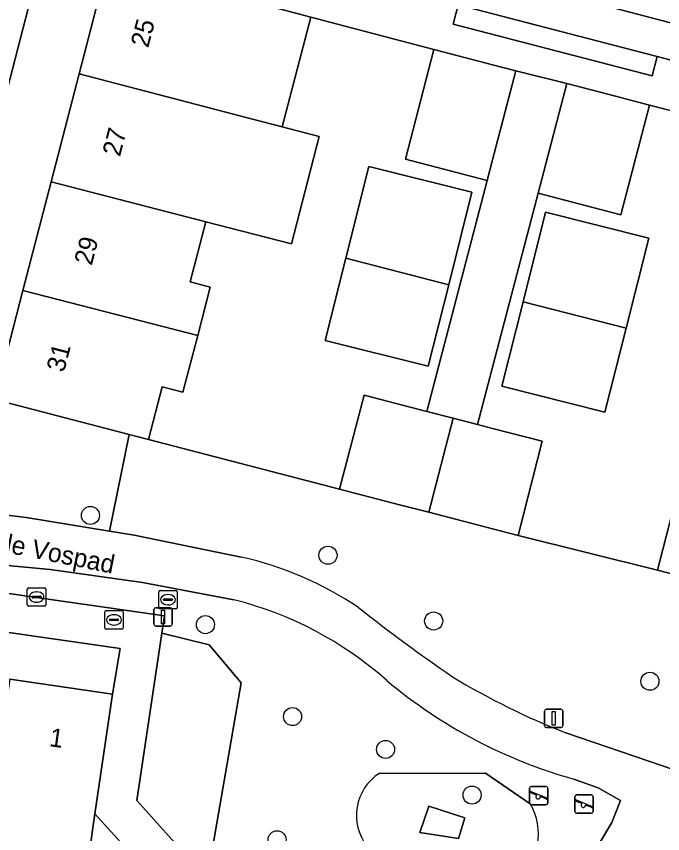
# Model space of a CAD drawing. Extents: x 163683 to 164494, y 382709 to 383872.
# Drawn here: x 163974.2 to 164009.22, y 383122.29 to 383166.57 of the extents above; entities that cross this region are included whole.
import ezdxf

# ---------------------------------------------------------------- set-up
doc = ezdxf.new("R2010")
doc.units = 0
for name, color, linetype in [('IMGEO_Boom', 7, 'Continuous'), ('IMGEO_Brandkraan', 7, 'Continuous'), ('IMGEO_Erf', 7, 'Continuous'), ('IMGEO_Groenvoorziening', 7, 'Continuous'), ('IMGEO_Kolk', 7, 'Continuous'), ('IMGEO_Lichtmast', 7, 'Continuous'), ('IMGEO_Muur', 7, 'Continuous'), ('IMGEO_Openbare_ruimte_label', 7, 'Continuous'), ('IMGEO_Pand', 7, 'Continuous'), ('IMGEO_Pand_nummerreeks', 7, 'Continuous'), ('IMGEO_Parkeervlak_open', 7, 'Continuous'), ('IMGEO_Rijbaan_lokaal_open', 7, 'Continuous'), ('IMGEO_Rioolput', 7, 'Continuous'), ('IMGEO_Speelvoorziening', 7, 'Continuous'), ('IMGEO_Voetpad_halfverhard', 7, 'Continuous'), ('IMGEO_Voetpad_open', 7, 'Continuous')]:
    doc.layers.add(name, color=color, linetype=linetype)

msp = doc.modelspace()

# ---------------------------------------------------------------- linework, layer by layer
at = {"layer": 'IMGEO_Boom'}
for centre in [(163978.219, 383139.529), (163991.09, 383137.372), (163984.452, 383133.612), (163996.817, 383133.81), (164008.535, 383130.543), (163989.172, 383128.63), (163994.213, 383126.85), (163998.895, 383124.375), (163988.332, 383121.956)]:
    msp.add_circle(centre, 0.489, dxfattribs=at)
at = {"layer": 'IMGEO_Brandkraan'}
for p, q in [((163978.993, 383133.446), (163978.993, 383134.298)), ((163979.068, 383134.372), (163979.92, 383134.372)), ((163979.481, 383134.152), (163979.506, 383134.152)), ((163979.994, 383134.298), (163979.994, 383133.446)), ((163979.252, 383133.866), (163979.252, 383133.878)), ((163979.69, 383133.829), (163979.292, 383133.829)), ((163979.295, 383133.915), (163979.693, 383133.915)), ((163979.504, 383133.592), (163979.479, 383133.592)), ((163979.736, 383133.878), (163979.736, 383133.866)), ((163979.92, 383133.372), (163979.068, 383133.372))]:
    msp.add_line(p, q, dxfattribs=at)
for points in [[(163978.993, 383133.446), (163978.993, 383134.298)], [(163979.068, 383134.372), (163979.92, 383134.372)], [(163979.994, 383134.298), (163979.994, 383133.446)], [(163979.92, 383133.372), (163979.068, 383133.372)]]:
    msp.add_lwpolyline(points, dxfattribs=at)
for centre, radius, start, end in [((163979.07, 383134.296), 0.0765, 91.552, 178.448), ((163979.07, 383134.296), 0.0765, 91.552, 178.448), ((163979.918, 383134.296), 0.0765, 1.552, 88.448), ((163979.918, 383134.296), 0.0765, 1.552, 88.448), ((163979.292, 383133.875), 0.0403, 85.8775, 175.7526), ((163979.289, 383133.865), 0.0366, 178.938, 274.7102), ((163979.693, 383133.872), 0.043, 264.8664, 352.4533), ((163979.697, 383133.877), 0.0386, 1.7309, 96.639), ((163979.07, 383133.448), 0.0765, 181.552, 268.448), ((163979.07, 383133.448), 0.0765, 181.552, 268.448), ((163979.918, 383133.448), 0.0765, 271.552, 358.448), ((163979.918, 383133.448), 0.0765, 271.552, 358.448)]:
    msp.add_arc(centre, radius, start, end, dxfattribs=at)
for centre, major_axis, ratio, start_param, end_param in [((163979.48, 383133.872), (-0.387, 0.002), 0.722429, 4.712389, 7.853982), ((163979.505, 383133.872), (-0.39, 0.002), 0.717154, 1.570796, 4.712389)]:
    msp.add_ellipse(centre, major_axis=major_axis, ratio=ratio, start_param=start_param, end_param=end_param, dxfattribs=at)
at = {"layer": 'IMGEO_Erf'}
for points in [[(163973.026, 383145.81), (163974.56, 383151.722), (163976.088, 383157.611), (163977.604, 383163.456), (163979.145, 383169.396), (163975.685, 383170.296), (163969.581, 383146.721)], [(163999.71, 383157.681), (163995.29, 383158.836), (163996.83, 383164.771), (163990.158, 383166.529), (163988.615, 383160.579), (163990.617, 383160.055), (163989.108, 383154.238), (163984.464, 383155.441), (163983.618, 383152.177), (163984.711, 383151.893), (163984.49, 383151.041), (163984.03, 383149.269), (163983.234, 383146.201), (163982.109, 383146.493), (163981.37, 383143.646), (163991.719, 383140.951), (163993.042, 383146.048), (163996.444, 383145.165)], [(164015.751, 383151.379), (164014.617, 383151.669), (164015.128, 383153.67), (164016.664, 383159.679), (164008.514, 383161.762), (164006.962, 383155.812), (164002.476, 383156.984), (163999.199, 383144.451), (163999.997, 383144.244), (164002.702, 383143.546), (164001.391, 383138.443), (164008.939, 383136.565), (164010.184, 383141.408), (164010.451, 383142.445), (164010.504, 383142.65), (164012.172, 383142.221), (164012.924, 383145.144), (164014.071, 383144.849), (164014.811, 383147.726)], [(163992.056, 383153.474), (163993.303, 383158.441), (163998.889, 383157.038), (163997.631, 383152.03), (163996.521, 383147.61), (163990.935, 383149.013)], [(164007.24, 383149.673), (164006.099, 383145.13), (164000.513, 383146.533), (164001.662, 383151.108), (164002.881, 383155.961), (164008.467, 383154.558)]]:
    msp.add_lwpolyline(points, close=True, dxfattribs=at)
for points in [[(163937.157, 383118.614), (163938.007, 383124.401), (163940.45, 383124.042), (163940.469, 383124.178), (163940.75, 383126.117), (163939.49, 383126.3), (163940.671, 383134.28), (163948.681, 383133.108), (163948.499, 383131.855), (163950.438, 383131.575), (163950.733, 383131.532), (163951.089, 383133.974), (163956.8, 383133.141), (163962.328, 383132.336), (163968.161, 383131.486), (163973.849, 383130.657), (163979.417, 383129.845), (163979.831, 383132.324), (163937.947, 383138.33), (163937.62, 383138.361), (163935.698, 383126.16), (163931.289, 383095.487)], [(163980.235, 383121.415), (163978.464, 383123.365), (163978.145, 383121.199)]]:
    msp.add_lwpolyline(points, dxfattribs=at)
at = {"layer": 'IMGEO_Groenvoorziening'}
for points in [[(163957.967, 383152.728), (163957.872, 383146.141), (163957.969, 383145.037), (163958.314, 383143.913), (163958.92, 383142.853), (163959.759, 383141.944), (163960.768, 383141.256), (163961.861, 383140.822), (163962.954, 383140.638), (163968.854, 383140.139), (163974.734, 383139.412), (163979.255, 383138.674), (163980.317, 383143.919), (163973.026, 383145.81), (163969.581, 383146.721), (163966.645, 383147.557), (163967.46, 383150.553), (163970.996, 383164.436)], [(164008.939, 383136.565), (164001.391, 383138.443), (164000, 383138.803), (163996.555, 383139.697), (163994.973, 383140.107), (163991.719, 383140.951), (163981.37, 383143.646), (163980.317, 383143.919), (163979.255, 383138.674), (163980.581, 383138.456), (163986.383, 383137.276)], [(163985.985, 383134.963), (163981.033, 383135.897), (163976.04, 383136.6), (163971.022, 383137.069), (163966.307, 383137.491), (163961.613, 383138.097), (163960.258, 383138.437), (163958.943, 383139.064), (163957.76, 383139.964), (163957.257, 383140.547), (163956.893, 383137.728), (163982.239, 383134.096), (163982.096, 383133.148), (163984.648, 383132.521), (163986.387, 383130.454), (163984.546, 383119.848)], [(164003.975, 383127.756), (164012.132, 383124.963), (164013.327, 383127.998), (164015.697, 383134.827), (164008.939, 383136.565)], [(164002.051, 383123.911), (163999.619, 383125.563), (163993.859, 383125.55)], [(163993.859, 383125.55), (163999.619, 383125.563), (164002.051, 383123.911)], [(164005.808, 383121.776), (164006.473, 383122.885), (164006.938, 383124.082), (164005.724, 383124.762), (164004.418, 383125.242)]]:
    msp.add_lwpolyline(points, dxfattribs=at)
for points in [[(163980.732, 383124.09), (163984.546, 383119.848), (163986.387, 383130.454), (163984.648, 383132.521), (163982.096, 383133.148)], [(163998.498, 383123.153), (163996.559, 383123.769), (163996.063, 383122.356), (163998.155, 383122.029)], [(163998.155, 383122.029), (163996.063, 383122.356), (163996.559, 383123.769), (163998.498, 383123.153)]]:
    msp.add_lwpolyline(points, close=True, dxfattribs=at)
for centre, radius, start, end in [((163982.283, 383118.963), 18.766, 56.1258, 77.3814), ((163981.171, 383115.806), 19.753, 48.4488, 75.8946), ((164049.451, 383206.077), 91.283, 231.59436, 235.56164), ((164011.704, 383151.367), 27.122, 230.0079, 254.4173), ((164018.313, 383164.526), 39.467, 238.7325, 248.698), ((163995.362, 383123.273), 2.728, 123.4303, 217.3759), ((163995.362, 383123.273), 2.728, 123.4303, 217.3759), ((163999.399, 383122.319), 3.093, 348.1472, 30.9693), ((163999.399, 383122.319), 3.093, 348.1472, 30.9693)]:
    msp.add_arc(centre, radius, start, end, dxfattribs=at)
at = {"layer": 'IMGEO_Kolk'}
for p, q in [((163974.799, 383134.681), (163974.799, 383135.533)), ((163974.874, 383135.607), (163975.726, 383135.607)), ((163975.287, 383135.387), (163975.312, 383135.387)), ((163975.8, 383135.533), (163975.8, 383134.681)), ((163975.058, 383135.101), (163975.058, 383135.113)), ((163975.496, 383135.064), (163975.098, 383135.064)), ((163975.101, 383135.15), (163975.499, 383135.15)), ((163975.542, 383135.113), (163975.542, 383135.101)), ((163975.726, 383134.607), (163974.874, 383134.607)), ((163975.31, 383134.827), (163975.285, 383134.827))]:
    msp.add_line(p, q, dxfattribs=at)
for points in [[(163974.799, 383134.681), (163974.799, 383135.533)], [(163974.874, 383135.607), (163975.726, 383135.607)], [(163975.8, 383135.533), (163975.8, 383134.681)], [(163975.726, 383134.607), (163974.874, 383134.607)]]:
    msp.add_lwpolyline(points, dxfattribs=at)
for centre, radius, start, end in [((163974.876, 383135.531), 0.0765, 91.552, 178.448), ((163974.876, 383135.531), 0.0765, 91.552, 178.448), ((163975.724, 383135.531), 0.0765, 1.552, 88.448), ((163975.724, 383135.531), 0.0765, 1.552, 88.448), ((163975.098, 383135.11), 0.0403, 85.8775, 175.7526), ((163975.095, 383135.1), 0.0366, 178.938, 274.7102), ((163975.499, 383135.107), 0.043, 264.8664, 352.4533), ((163975.503, 383135.112), 0.0386, 1.7309, 96.639), ((163974.876, 383134.683), 0.0765, 181.552, 268.448), ((163974.876, 383134.683), 0.0765, 181.552, 268.448), ((163975.724, 383134.683), 0.0765, 271.552, 358.448), ((163975.724, 383134.683), 0.0765, 271.552, 358.448)]:
    msp.add_arc(centre, radius, start, end, dxfattribs=at)
for centre, major_axis, ratio, start_param, end_param in [((163975.286, 383135.107), (-0.387, 0.002), 0.722429, 4.712389, 7.853982), ((163975.311, 383135.107), (-0.39, 0.002), 0.717154, 1.570796, 4.712389)]:
    msp.add_ellipse(centre, major_axis=major_axis, ratio=ratio, start_param=start_param, end_param=end_param, dxfattribs=at)
at = {"layer": 'IMGEO_Lichtmast'}
for p, q in [((163981.654, 383133.629), (163981.654, 383134.429)), ((163981.654, 383134.429), (163981.654, 383133.629)), ((163981.754, 383134.529), (163982.544, 383134.529)), ((163982.544, 383134.529), (163981.754, 383134.529)), ((163982.644, 383134.429), (163982.644, 383133.629)), ((163982.644, 383133.629), (163982.644, 383134.429)), ((163982.544, 383133.529), (163981.754, 383133.529)), ((163981.754, 383133.529), (163982.544, 383133.529)), ((164002.825, 383128.133), (164002.825, 383128.933)), ((164002.825, 383128.933), (164002.825, 383128.133)), ((164002.925, 383129.033), (164003.715, 383129.033)), ((164003.715, 383129.033), (164002.925, 383129.033)), ((164003.815, 383128.933), (164003.815, 383128.133)), ((164003.815, 383128.133), (164003.815, 383128.933)), ((164003.715, 383128.033), (164002.925, 383128.033)), ((164002.925, 383128.033), (164003.715, 383128.033))]:
    msp.add_line(p, q, dxfattribs=at)
for points in [[(163982.074, 383134.404), (163982.224, 383134.404), (163982.224, 383133.654), (163982.074, 383133.654), (163982.074, 383134.404)], [(164003.245, 383128.908), (164003.395, 383128.908), (164003.395, 383128.158), (164003.245, 383128.158), (164003.245, 383128.908)]]:
    msp.add_lwpolyline(points, dxfattribs=at)
for centre, start, end in [((163981.754, 383134.429), 90, 180), ((163981.754, 383134.429), 90, 180), ((163982.544, 383134.429), 0, 90), ((163982.544, 383134.429), 360, 90), ((163981.754, 383133.629), 180, 270), ((163981.754, 383133.629), 180, 270), ((163982.544, 383133.629), 270, 0), ((163982.544, 383133.629), 270, 0), ((164002.925, 383128.933), 90, 180), ((164002.925, 383128.933), 90, 180), ((164003.715, 383128.933), 0, 90), ((164003.715, 383128.933), 360, 90), ((164002.925, 383128.133), 180, 270), ((164002.925, 383128.133), 180, 270), ((164003.715, 383128.133), 270, 0), ((164003.715, 383128.133), 270, 0)]:
    msp.add_arc(centre, 0.1, start, end, dxfattribs=at)
at = {"layer": 'IMGEO_Muur'}
for points in [[(163990.158, 383166.529), (163996.83, 383164.771)], [(164008.514, 383161.762), (164016.664, 383159.679)], [(163981.37, 383143.646), (163991.719, 383140.951)], [(164001.391, 383138.443), (164008.939, 383136.565)]]:
    msp.add_lwpolyline(points, dxfattribs=at)
at = {"layer": 'IMGEO_Pand'}
for points in [[(163990.158, 383166.529), (163987.504, 383167.228), (163979.145, 383169.396), (163977.604, 383163.456), (163987.078, 383160.981), (163988.615, 383160.579)], [(163998.556, 383164.323), (163996.83, 383164.771), (163995.29, 383158.836), (163999.71, 383157.681), (164000, 383158.793), (164001.26, 383163.621), (164000, 383163.949)], [(163988.615, 383160.579), (163987.078, 383160.981), (163977.604, 383163.456), (163976.088, 383157.611), (163984.464, 383155.441), (163989.108, 383154.238), (163990.617, 383160.055)], [(164004.028, 383162.933), (164002.476, 383156.984), (164006.962, 383155.812), (164008.514, 383161.762), (164006.672, 383162.243)], [(163992.056, 383153.474), (163997.631, 383152.03), (163998.889, 383157.038), (163993.303, 383158.441)], [(163974.56, 383151.722), (163984.03, 383149.269), (163984.49, 383151.041), (163984.711, 383151.893), (163983.618, 383152.177), (163984.464, 383155.441), (163976.088, 383157.611)], [(164007.24, 383149.673), (164008.467, 383154.558), (164002.881, 383155.961), (164001.662, 383151.108)], [(163992.056, 383153.474), (163990.935, 383149.013), (163996.521, 383147.61), (163997.631, 383152.03)], [(163974.56, 383151.722), (163973.026, 383145.81), (163980.317, 383143.919), (163981.37, 383143.646), (163982.109, 383146.493), (163983.234, 383146.201), (163984.03, 383149.269)], [(164007.24, 383149.673), (164001.662, 383151.108), (164000.513, 383146.533), (164006.099, 383145.13)], [(163996.555, 383139.697), (163997.875, 383144.794), (163996.444, 383145.165), (163993.042, 383146.048), (163991.719, 383140.951), (163994.973, 383140.107)], [(163996.555, 383139.697), (164000, 383138.803), (164001.391, 383138.443), (164002.702, 383143.546), (163999.997, 383144.244), (163999.199, 383144.451), (163997.875, 383144.794)], [(164021.795, 383139.746), (164013.319, 383141.926), (164012.172, 383142.221), (164010.504, 383142.65), (164010.451, 383142.445), (164010.184, 383141.408), (164008.939, 383136.565), (164015.697, 383134.827), (164020.23, 383133.661)], [(163973.849, 383130.657), (163972.579, 383122.01), (163973.284, 383121.907), (163978.145, 383121.199), (163978.464, 383123.365), (163979.417, 383129.845)]]:
    msp.add_lwpolyline(points, close=True, dxfattribs=at)
at = {"layer": 'IMGEO_Parkeervlak_open'}
for points in [[(164026.298, 383161.922), (164019.302, 383163.696), (163976.377, 383174.954)], [(163978.847, 383172.238), (163998.15, 383167.201), (164008.929, 383164.4), (164022.413, 383160.855)]]:
    msp.add_lwpolyline(points, dxfattribs=at)
at = {"layer": 'IMGEO_Rijbaan_lokaal_open'}
msp.add_lwpolyline([(163976.377, 383174.954), (164019.302, 383163.696), (164026.298, 383161.922), (164026.544, 383161.859), (164027.754, 383161.546)], dxfattribs=at)
msp.add_lwpolyline([(163996.444, 383145.165), (163997.875, 383144.794), (163999.199, 383144.451), (164002.476, 383156.984), (164004.028, 383162.933), (164001.26, 383163.621), (164000, 383158.793), (163999.71, 383157.681)], close=True, dxfattribs=at)
at = {"layer": 'IMGEO_Rioolput'}
for p, q in [((163981.922, 383134.538), (163981.922, 383135.39)), ((163981.997, 383135.464), (163982.849, 383135.464)), ((163982.923, 383135.39), (163982.923, 383134.538)), ((163982.181, 383134.958), (163982.181, 383134.97)), ((163982.619, 383134.921), (163982.221, 383134.921)), ((163982.224, 383135.007), (163982.622, 383135.007)), ((163982.41, 383135.244), (163982.435, 383135.244)), ((163982.665, 383134.97), (163982.665, 383134.958)), ((163982.849, 383134.464), (163981.997, 383134.464)), ((163982.433, 383134.684), (163982.408, 383134.684))]:
    msp.add_line(p, q, dxfattribs=at)
for points in [[(163981.922, 383134.538), (163981.922, 383135.39)], [(163981.997, 383135.464), (163982.849, 383135.464)], [(163982.923, 383135.39), (163982.923, 383134.538)], [(163982.849, 383134.464), (163981.997, 383134.464)]]:
    msp.add_lwpolyline(points, dxfattribs=at)
for centre, radius, start, end in [((163981.999, 383135.388), 0.0765, 91.552, 178.448), ((163981.999, 383135.388), 0.0765, 91.552, 178.448), ((163982.847, 383135.388), 0.0765, 1.552, 88.448), ((163982.847, 383135.388), 0.0765, 1.552, 88.448), ((163982.221, 383134.967), 0.0403, 85.8775, 175.7526), ((163982.218, 383134.957), 0.0366, 178.938, 274.7102), ((163982.622, 383134.964), 0.043, 264.8664, 352.4533), ((163982.626, 383134.969), 0.0386, 1.7309, 96.639), ((163981.999, 383134.54), 0.0765, 181.552, 268.448), ((163981.999, 383134.54), 0.0765, 181.552, 268.448), ((163982.847, 383134.54), 0.0765, 271.552, 358.448), ((163982.847, 383134.54), 0.0765, 271.552, 358.448)]:
    msp.add_arc(centre, radius, start, end, dxfattribs=at)
for centre, major_axis, ratio, start_param, end_param in [((163982.409, 383134.964), (-0.387, 0.002), 0.722429, 4.712389, 7.853982), ((163982.434, 383134.964), (-0.39, 0.002), 0.717154, 1.570796, 4.712389)]:
    msp.add_ellipse(centre, major_axis=major_axis, ratio=ratio, start_param=start_param, end_param=end_param, dxfattribs=at)
at = {"layer": 'IMGEO_Speelvoorziening'}
for p, q in [((164002.01, 383123.948), (164002.01, 383124.748)), ((164002.01, 383124.748), (164002.01, 383123.948)), ((164002.11, 383124.848), (164002.9, 383124.848)), ((164002.9, 383124.848), (164002.11, 383124.848)), ((164003, 383124.748), (164003, 383123.948)), ((164003, 383123.948), (164003, 383124.748)), ((164002.393, 383124.376), (164002.054, 383124.513)), ((164002.079, 383124.573), (164002.955, 383124.22)), ((164002.931, 383124.16), (164002.591, 383124.297)), ((164004.464, 383123.49), (164004.464, 383124.29)), ((164004.464, 383124.29), (164004.464, 383123.49)), ((164004.564, 383124.39), (164005.354, 383124.39)), ((164005.354, 383124.39), (164004.564, 383124.39)), ((164005.454, 383124.29), (164005.454, 383123.49)), ((164005.454, 383123.49), (164005.454, 383124.29)), ((164002.9, 383123.848), (164002.11, 383123.848)), ((164002.11, 383123.848), (164002.9, 383123.848)), ((164004.847, 383123.918), (164004.508, 383124.055)), ((164004.533, 383124.115), (164005.409, 383123.762)), ((164005.385, 383123.702), (164005.045, 383123.839)), ((164005.354, 383123.39), (164004.564, 383123.39)), ((164004.564, 383123.39), (164005.354, 383123.39))]:
    msp.add_line(p, q, dxfattribs=at)
for centre, radius, start, end in [((164002.11, 383124.748), 0.1, 90, 180), ((164002.11, 383124.748), 0.1, 90, 180), ((164002.9, 383124.748), 0.1, 0, 90), ((164002.9, 383124.748), 0.1, 360, 90), ((164002.067, 383124.543), 0.0327, 68.078, 248.078), ((164002.472, 383124.286), 0.12, 130.9928, 5.1632), ((164002.943, 383124.19), 0.0327, 248.078, 68.078), ((164004.564, 383124.29), 0.1, 90, 180), ((164004.564, 383124.29), 0.1, 90, 180), ((164005.354, 383124.29), 0.1, 0, 90), ((164005.354, 383124.29), 0.1, 360, 90), ((164002.11, 383123.948), 0.1, 180, 270), ((164002.11, 383123.948), 0.1, 180, 270), ((164002.9, 383123.948), 0.1, 270, 0), ((164002.9, 383123.948), 0.1, 270, 0), ((164004.521, 383124.085), 0.0327, 68.078, 248.078), ((164004.926, 383123.828), 0.12, 130.9928, 5.1632), ((164004.564, 383123.49), 0.1, 180, 270), ((164004.564, 383123.49), 0.1, 180, 270), ((164005.354, 383123.49), 0.1, 270, 0), ((164005.354, 383123.49), 0.1, 270, 0), ((164005.397, 383123.732), 0.0327, 248.078, 68.078)]:
    msp.add_arc(centre, radius, start, end, dxfattribs=at)
at = {"layer": 'IMGEO_Voetpad_halfverhard'}
for points in [[(163986.383, 383137.276), (163980.581, 383138.456), (163979.255, 383138.674), (163974.734, 383139.412), (163968.854, 383140.139), (163962.954, 383140.638), (163961.861, 383140.822), (163960.768, 383141.256), (163959.759, 383141.944), (163958.92, 383142.853), (163958.314, 383143.913), (163957.969, 383145.037), (163957.872, 383146.141), (163957.967, 383152.728)], [(163971.022, 383137.069), (163976.04, 383136.6), (163981.033, 383135.897), (163985.985, 383134.963)], [(164012.132, 383124.963), (164003.975, 383127.756)], [(164004.418, 383125.242), (164005.724, 383124.762), (164006.938, 383124.082), (164006.473, 383122.885), (164005.808, 383121.776), (164004.971, 383120.801), (163995.816, 383111.794), (163989.902, 383106.278), (163988.055, 383093.357), (163988.304, 383093.335)]]:
    msp.add_lwpolyline(points, dxfattribs=at)
for centre, radius, start, end in [((163982.283, 383118.963), 18.766, 56.1258, 77.3814), ((163981.171, 383115.806), 19.753, 48.4488, 75.8946), ((164049.451, 383206.077), 91.283, 231.59436, 235.56164), ((164011.704, 383151.367), 27.122, 230.0079, 254.4173), ((164018.313, 383164.526), 39.467, 238.7325, 248.698)]:
    msp.add_arc(centre, radius, start, end, dxfattribs=at)
at = {"layer": 'IMGEO_Voetpad_open'}
for points in [[(164022.413, 383160.855), (164008.929, 383164.4), (164008.652, 383163.346), (163997.873, 383166.152), (163998.15, 383167.201), (163978.847, 383172.238)], [(163969.581, 383146.721), (163975.685, 383170.296), (163979.145, 383169.396), (163987.504, 383167.228), (163990.158, 383166.529), (163996.83, 383164.771), (163998.556, 383164.323), (164000, 383163.949), (164001.26, 383163.621), (164004.028, 383162.933), (164006.672, 383162.243), (164008.514, 383161.762), (164016.664, 383159.679), (164017.81, 383159.386), (164026.286, 383157.206), (164029.771, 383156.297), (164023.717, 383132.762), (164026.062, 383132.169), (164026.707, 383132.006), (164031.927, 383152.313), (164032.775, 383155.553), (164033.039, 383156.561)], [(163984.546, 383119.848), (163980.732, 383124.09), (163982.096, 383133.148), (163982.239, 383134.096), (163956.893, 383137.728), (163939.189, 383140.265), (163939.058, 383140.284), (163938.151, 383140.429), (163937.62, 383138.361), (163937.947, 383138.33), (163979.831, 383132.324), (163979.417, 383129.845), (163978.464, 383123.365), (163980.235, 383121.415)]]:
    msp.add_lwpolyline(points, dxfattribs=at)
msp.add_lwpolyline([(163998.15, 383167.201), (163997.873, 383166.152), (164008.652, 383163.346), (164008.929, 383164.4)], close=True, dxfattribs=at)

# ---------------------------------------------------------------- texts
at = {"layer": 'IMGEO_Openbare_ruimte_label'}
msp.add_text('Cornelis de Vospad', height=1, rotation=348.7013, dxfattribs=at).set_placement((163967.976, 383138.656))
at = {"layer": 'IMGEO_Pand_nummerreeks'}
for s, rotation, p in [('25', 75.4585, (163981.347, 383164.825)), ('27', 75.4585, (163979.817, 383158.928)), ('29', 75.4562, (163978.288, 383153.032)), ('31', 75.4562, (163976.787, 383147.244)), ('1', 351.7077, (163975.951, 383127.035))]:
    msp.add_text(s, height=1, rotation=rotation, dxfattribs=at).set_placement(p)

doc.saveas('drawing.dxf')
